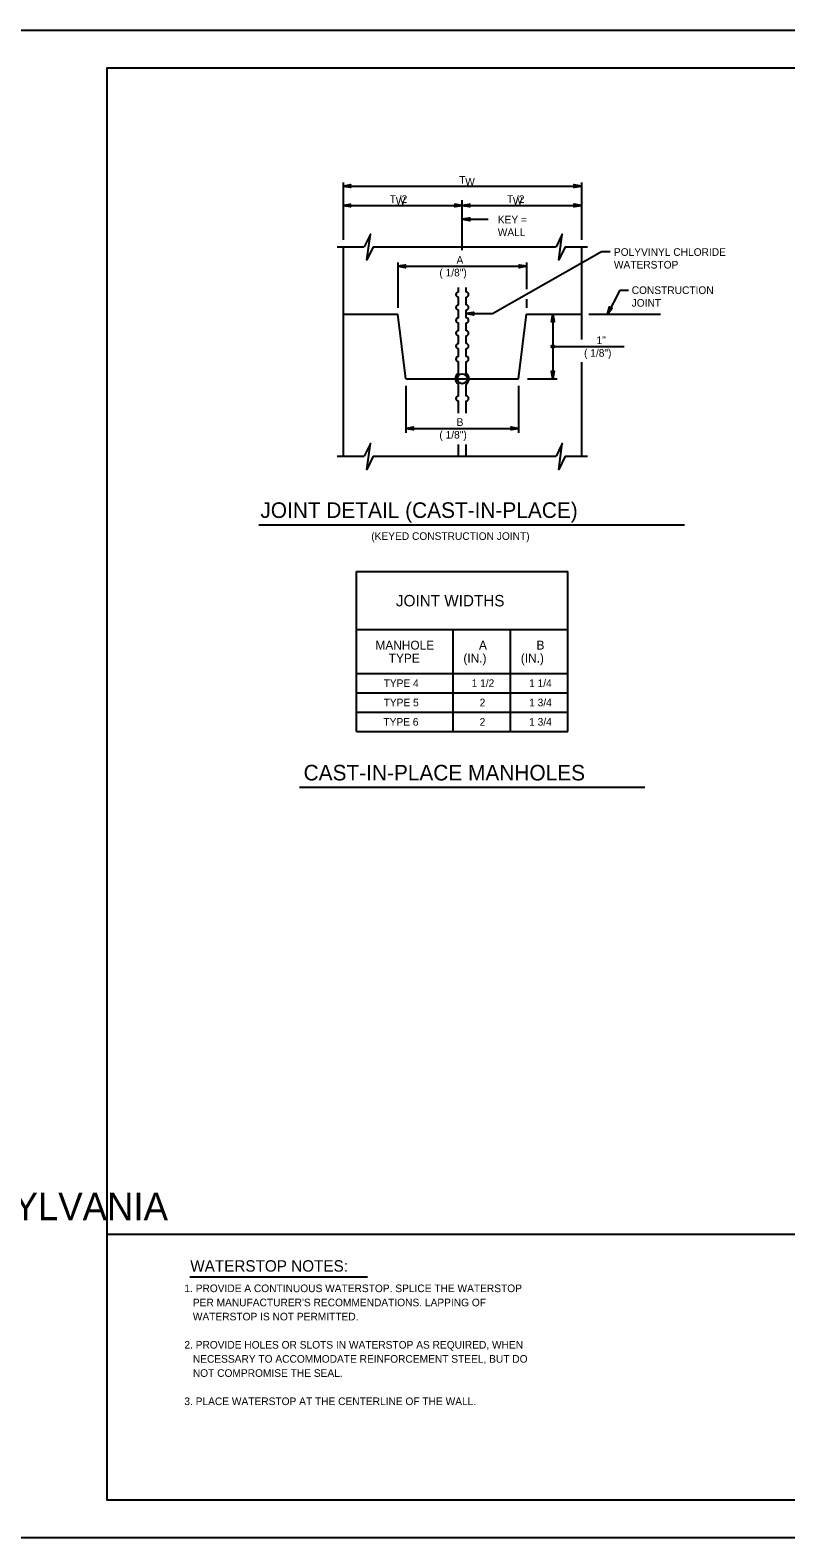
# Model space of a CAD drawing. Extents: x 2106427 to 2114911, y 988717 to 990787.
# Drawn here: x 2111974 to 2112951, y 988839 to 990787 of the extents above; entities that cross this region are included whole.
import ezdxf

# ---------------------------------------------------------------- set-up
doc = ezdxf.new("R2010")
doc.units = 0
for name, color, linetype in [('1', 7, 'Continuous'), ('3', 7, 'Continuous'), ('PLT-BNDY', 7, 'Continuous')]:
    doc.layers.add(name, color=color, linetype=linetype)

msp = doc.modelspace()

# ---------------------------------------------------------------- linework, layer by layer
at = {"layer": '1'}
for p, q in [((2112378.6, 990590.2), (2112378.6, 990516.5)), ((2112378.6, 990585.8), (2112686.7, 990585.8)), ((2112686.7, 990590.2), (2112686.7, 990516.5)), ((2112532.6, 990502.9), (2112532.6, 990567.6)), ((2112378.6, 990560.8), (2112532.6, 990560.8)), ((2112532.6, 990560.8), (2112686.7, 990560.8)), ((2112532.6, 990542.9), (2112566.2, 990542.9)), ((2112371, 990507.3), (2112406, 990507.3)), ((2112378.6, 990507.3), (2112378.6, 990236.6)), ((2112417.6, 990507.3), (2112654.2, 990507.3)), ((2112665.8, 990507.3), (2112694.5, 990507.3)), ((2112686.7, 990507.3), (2112686.7, 990387.6)), ((2112571.6, 990421), (2112712.8, 990501)), ((2112712.8, 990501), (2112724.1, 990501)), ((2112449.3, 990487.2), (2112449.3, 990428.6)), ((2112449.3, 990482.1), (2112615.9, 990482.1)), ((2112615.9, 990487.2), (2112615.9, 990452.5)), ((2112527.6, 990448.8), (2112527.6, 990454.8)), ((2112537.6, 990448.8), (2112537.6, 990454.8)), ((2112736.4, 990451.1), (2112720.4, 990420)), ((2112736.4, 990451.1), (2112747.7, 990451.1)), ((2112527.6, 990432.2), (2112527.6, 990442.3)), ((2112537.6, 990432.2), (2112537.6, 990442.3)), ((2112615.9, 990439.7), (2112615.9, 990428.6)), ((2112378.6, 990420), (2112449.3, 990420)), ((2112459.7, 990336.7), (2112449.3, 990420)), ((2112527.6, 990415.5), (2112527.6, 990425.7)), ((2112537.6, 990415.5), (2112537.6, 990425.7)), ((2112537.6, 990421), (2112571.6, 990421)), ((2112605.5, 990336.7), (2112615.9, 990420)), ((2112615.9, 990420), (2112686.7, 990420)), ((2112649.9, 990420), (2112649.9, 990336.7)), ((2112696.4, 990420), (2112789.2, 990420)), ((2112527.6, 990398.8), (2112527.6, 990409)), ((2112527.6, 990382.1), (2112527.6, 990392.3)), ((2112537.6, 990398.8), (2112537.6, 990409)), ((2112537.6, 990382.1), (2112537.6, 990392.3)), ((2112527.6, 990365.5), (2112527.6, 990375.7)), ((2112537.6, 990365.5), (2112537.6, 990375.7)), ((2112649.9, 990378.3), (2112742.2, 990378.3)), ((2112527.6, 990344), (2112527.6, 990359)), ((2112537.6, 990344), (2112537.6, 990359)), ((2112686.7, 990358.2), (2112686.7, 990236.6)), ((2112459.7, 990336.7), (2112605.5, 990336.7)), ((2112617.1, 990336.7), (2112655.6, 990336.7)), ((2112459.7, 990327.7), (2112459.7, 990267)), ((2112527.6, 990314.4), (2112527.6, 990329.4)), ((2112537.6, 990314.4), (2112537.6, 990329.4)), ((2112605.5, 990327.7), (2112605.5, 990267)), ((2112527.6, 990292.2), (2112527.6, 990308)), ((2112537.6, 990292.2), (2112537.6, 990308)), ((2112459.7, 990272.5), (2112605.5, 990272.5)), ((2112371, 990236.6), (2112406, 990236.6)), ((2112417.6, 990236.6), (2112654.2, 990236.6)), ((2112527.6, 990236.6), (2112527.6, 990251.8)), ((2112537.6, 990236.6), (2112537.6, 990251.8)), ((2112665.8, 990236.6), (2112694.5, 990236.6)), ((2112269.5, 990148.1), (2112820.2, 990148.1)), ((2112395.9, 989880.7), (2112395.9, 990087.4)), ((2112395.9, 990087.4), (2112669.4, 990087.4)), ((2112669.4, 989880.7), (2112669.4, 990087.4)), ((2112395.9, 990012.4), (2112669.4, 990012.4)), ((2112520.9, 989880.7), (2112520.9, 990012.4)), ((2112595.2, 989880.7), (2112595.2, 990012.4)), ((2112395.9, 989955.7), (2112669.4, 989955.7)), ((2112395.9, 989930.7), (2112669.4, 989930.7)), ((2112395.9, 989905.7), (2112669.4, 989905.7)), ((2112395.9, 989880.7), (2112669.4, 989880.7)), ((2112322.1, 989808.8), (2112768.6, 989808.8)), ((2112072.8, 989231), (2113995.4, 989231)), ((2112180.2, 989175.8), (2112410.3, 989175.8))]:
    msp.add_line(p, q, dxfattribs=at)
for points in [[(2114651.6, 988887.7), (2114651.6, 990738.1), (2112072.8, 990738.1), (2112072.8, 988887.7), (2114651.6, 988887.7), (2114651.6, 988974.2), (2113995.4, 988974.2), (2113995.4, 989186.4), (2114651.6, 989186.4), (2114651.6, 989281.4), (2113995.4, 989281.4), (2113995.4, 988887.7), (2114253.9, 988887.7), (2114253.9, 988974.2), (2114253.9, 988887.7), (2114506.6, 988887.7), (2114506.6, 988974.2), (2114506.6, 988933.8), (2114651.6, 988933.8)], [(2112378.6, 990585.8), (2112388.3, 990587.6), (2112388, 990587.4), (2112387.6, 990587.1), (2112387.4, 990586.8), (2112387.2, 990586.4), (2112387.1, 990586.1), (2112387.1, 990585.8), (2112387.1, 990585.5), (2112387.2, 990585.1), (2112387.4, 990584.8), (2112387.6, 990584.5), (2112388, 990584.2), (2112388.3, 990584), (2112378.6, 990585.8), (2112388, 990584.2), (2112387.6, 990584.5), (2112378.6, 990585.8), (2112387.4, 990584.8), (2112387.2, 990585.1), (2112378.6, 990585.8), (2112387.1, 990585.5), (2112387.1, 990585.8), (2112378.6, 990585.8), (2112387.1, 990586.1), (2112387.2, 990586.4), (2112378.6, 990585.8), (2112387.4, 990586.8), (2112387.6, 990587.1), (2112378.6, 990585.8), (2112388, 990587.4)], [(2112686.7, 990585.8), (2112676.9, 990584), (2112677.3, 990584.2), (2112677.7, 990584.5), (2112677.9, 990584.8), (2112678.1, 990585.1), (2112678.1, 990585.5), (2112678.2, 990585.8), (2112678.1, 990586.1), (2112678.1, 990586.4), (2112677.9, 990586.8), (2112677.7, 990587.1), (2112677.3, 990587.4), (2112676.9, 990587.6), (2112686.7, 990585.8), (2112677.3, 990587.4), (2112677.7, 990587.1), (2112686.7, 990585.8), (2112677.9, 990586.8), (2112678.1, 990586.4), (2112686.7, 990585.8), (2112678.1, 990586.1), (2112678.2, 990585.8), (2112686.7, 990585.8), (2112678.1, 990585.5), (2112678.1, 990585.1), (2112686.7, 990585.8), (2112677.9, 990584.8), (2112677.7, 990584.5), (2112686.7, 990585.8), (2112677.3, 990584.2)], [(2112378.6, 990560.8), (2112388.3, 990562.6), (2112388, 990562.4), (2112387.6, 990562.1), (2112387.4, 990561.8), (2112387.2, 990561.4), (2112387.1, 990561.1), (2112387.1, 990560.8), (2112387.1, 990560.5), (2112387.2, 990560.1), (2112387.4, 990559.8), (2112387.6, 990559.5), (2112388, 990559.2), (2112388.3, 990559), (2112378.6, 990560.8), (2112388, 990559.2), (2112387.6, 990559.5), (2112378.6, 990560.8), (2112387.4, 990559.8), (2112387.2, 990560.1), (2112378.6, 990560.8), (2112387.1, 990560.5), (2112387.1, 990560.8), (2112378.6, 990560.8), (2112387.1, 990561.1), (2112387.2, 990561.4), (2112378.6, 990560.8), (2112387.4, 990561.8), (2112387.6, 990562.1), (2112378.6, 990560.8), (2112388, 990562.4)], [(2112532.6, 990560.8), (2112522.9, 990559), (2112523.2, 990559.2), (2112523.6, 990559.5), (2112523.8, 990559.8), (2112524, 990560.1), (2112524.1, 990560.5), (2112524.1, 990560.8), (2112524.1, 990561.1), (2112524, 990561.4), (2112523.8, 990561.8), (2112523.6, 990562.1), (2112523.2, 990562.4), (2112522.9, 990562.6), (2112532.6, 990560.8), (2112523.2, 990562.4), (2112523.6, 990562.1), (2112532.6, 990560.8), (2112523.8, 990561.8), (2112524, 990561.4), (2112532.6, 990560.8), (2112524.1, 990561.1), (2112524.1, 990560.8), (2112532.6, 990560.8), (2112524.1, 990560.5), (2112524, 990560.1), (2112532.6, 990560.8), (2112523.8, 990559.8), (2112523.6, 990559.5), (2112532.6, 990560.8), (2112523.2, 990559.2)], [(2112532.6, 990560.8), (2112542.4, 990562.6), (2112542, 990562.4), (2112541.7, 990562.1), (2112541.5, 990561.8), (2112541.3, 990561.4), (2112541.2, 990561.1), (2112541.2, 990560.8), (2112541.2, 990560.5), (2112541.3, 990560.1), (2112541.5, 990559.8), (2112541.7, 990559.5), (2112542, 990559.2), (2112542.4, 990559), (2112532.6, 990560.8), (2112542, 990559.2), (2112541.7, 990559.5), (2112532.6, 990560.8), (2112541.5, 990559.8), (2112541.3, 990560.1), (2112532.6, 990560.8), (2112541.2, 990560.5), (2112541.2, 990560.8), (2112532.6, 990560.8), (2112541.2, 990561.1), (2112541.3, 990561.4), (2112532.6, 990560.8), (2112541.5, 990561.8), (2112541.7, 990562.1), (2112532.6, 990560.8), (2112542, 990562.4)], [(2112686.7, 990560.8), (2112676.9, 990559), (2112677.3, 990559.2), (2112677.7, 990559.5), (2112677.9, 990559.8), (2112678.1, 990560.1), (2112678.1, 990560.5), (2112678.2, 990560.8), (2112678.1, 990561.1), (2112678.1, 990561.4), (2112677.9, 990561.8), (2112677.7, 990562.1), (2112677.3, 990562.4), (2112676.9, 990562.6), (2112686.7, 990560.8), (2112677.3, 990562.4), (2112677.7, 990562.1), (2112686.7, 990560.8), (2112677.9, 990561.8), (2112678.1, 990561.4), (2112686.7, 990560.8), (2112678.1, 990561.1), (2112678.2, 990560.8), (2112686.7, 990560.8), (2112678.1, 990560.5), (2112678.1, 990560.1), (2112686.7, 990560.8), (2112677.9, 990559.8), (2112677.7, 990559.5), (2112686.7, 990560.8), (2112677.3, 990559.2)], [(2112532.6, 990542.9), (2112542.4, 990544.7), (2112542, 990544.4), (2112541.7, 990544.2), (2112541.5, 990543.8), (2112541.3, 990543.5), (2112541.2, 990543.2), (2112541.2, 990542.9), (2112541.2, 990542.5), (2112541.3, 990542.2), (2112541.5, 990541.9), (2112541.7, 990541.5), (2112542, 990541.3), (2112542.4, 990541), (2112532.6, 990542.9), (2112542, 990541.3), (2112541.7, 990541.5), (2112532.6, 990542.9), (2112541.5, 990541.9), (2112541.3, 990542.2), (2112532.6, 990542.9), (2112541.2, 990542.5), (2112541.2, 990542.9), (2112532.6, 990542.9), (2112541.2, 990543.2), (2112541.3, 990543.5), (2112532.6, 990542.9), (2112541.5, 990543.8), (2112541.7, 990544.2), (2112532.6, 990542.9), (2112542, 990544.4)], [(2112417.6, 990507.3), (2112409.2, 990490.3), (2112413.8, 990523.6), (2112406, 990507.3)], [(2112665.8, 990507.3), (2112657.4, 990490.3), (2112662, 990523.6), (2112654.2, 990507.3)], [(2112449.3, 990482.1), (2112459.1, 990483.9), (2112458.7, 990483.7), (2112458.4, 990483.4), (2112458.2, 990483.1), (2112458, 990482.8), (2112457.9, 990482.4), (2112457.9, 990482.1), (2112457.9, 990481.8), (2112458, 990481.4), (2112458.2, 990481.1), (2112458.4, 990480.8), (2112458.7, 990480.5), (2112459.1, 990480.3), (2112449.3, 990482.1), (2112458.7, 990480.5), (2112458.4, 990480.8), (2112449.3, 990482.1), (2112458.2, 990481.1), (2112458, 990481.4), (2112449.3, 990482.1), (2112457.9, 990481.8), (2112457.9, 990482.1), (2112449.3, 990482.1), (2112457.9, 990482.4), (2112458, 990482.8), (2112449.3, 990482.1), (2112458.2, 990483.1), (2112458.4, 990483.4), (2112449.3, 990482.1), (2112458.7, 990483.7)], [(2112615.9, 990482.1), (2112606.2, 990480.3), (2112606.5, 990480.5), (2112606.9, 990480.8), (2112607.1, 990481.1), (2112607.3, 990481.4), (2112607.4, 990481.8), (2112607.4, 990482.1), (2112607.4, 990482.4), (2112607.3, 990482.8), (2112607.1, 990483.1), (2112606.9, 990483.4), (2112606.5, 990483.7), (2112606.2, 990483.9), (2112615.9, 990482.1), (2112606.5, 990483.7), (2112606.9, 990483.4), (2112615.9, 990482.1), (2112607.1, 990483.1), (2112607.3, 990482.8), (2112615.9, 990482.1), (2112607.4, 990482.4), (2112607.4, 990482.1), (2112615.9, 990482.1), (2112607.4, 990481.8), (2112607.3, 990481.4), (2112615.9, 990482.1), (2112607.1, 990481.1), (2112606.9, 990480.8), (2112615.9, 990482.1), (2112606.5, 990480.5)], [(2112720.4, 990420), (2112723.3, 990429.5), (2112723.3, 990429.1), (2112723.4, 990428.6), (2112723.6, 990428.3), (2112723.8, 990428), (2112724.1, 990427.8), (2112724.3, 990427.6), (2112724.7, 990427.5), (2112725, 990427.4), (2112725.3, 990427.4), (2112725.7, 990427.4), (2112726.1, 990427.7), (2112726.5, 990427.9), (2112720.4, 990420), (2112726.1, 990427.7), (2112725.7, 990427.4), (2112720.4, 990420), (2112725.3, 990427.4), (2112725, 990427.4), (2112720.4, 990420), (2112724.7, 990427.5), (2112724.3, 990427.6), (2112720.4, 990420), (2112724.1, 990427.8), (2112723.8, 990428), (2112720.4, 990420), (2112723.6, 990428.3), (2112723.4, 990428.6), (2112720.4, 990420), (2112723.3, 990429.1)], [(2112537.6, 990421), (2112547.4, 990422.8), (2112547, 990422.5), (2112546.7, 990422.3), (2112546.5, 990421.9), (2112546.3, 990421.6), (2112546.2, 990421.3), (2112546.2, 990421), (2112546.2, 990420.6), (2112546.3, 990420.3), (2112546.5, 990420), (2112546.7, 990419.6), (2112547, 990419.4), (2112547.4, 990419.1), (2112537.6, 990421), (2112547, 990419.4), (2112546.7, 990419.6), (2112537.6, 990421), (2112546.5, 990420), (2112546.3, 990420.3), (2112537.6, 990421), (2112546.2, 990420.6), (2112546.2, 990421), (2112537.6, 990421), (2112546.2, 990421.3), (2112546.3, 990421.6), (2112537.6, 990421), (2112546.5, 990421.9), (2112546.7, 990422.3), (2112537.6, 990421), (2112547, 990422.5)], [(2112649.9, 990420), (2112651.7, 990410.2), (2112651.5, 990410.6), (2112651.2, 990411), (2112650.9, 990411.2), (2112650.6, 990411.4), (2112650.2, 990411.4), (2112649.9, 990411.5), (2112649.6, 990411.4), (2112649.2, 990411.4), (2112648.9, 990411.2), (2112648.6, 990411), (2112648.3, 990410.6), (2112648.1, 990410.2), (2112649.9, 990420), (2112648.3, 990410.6), (2112648.6, 990411), (2112649.9, 990420), (2112648.9, 990411.2), (2112649.2, 990411.4), (2112649.9, 990420), (2112649.6, 990411.4), (2112649.9, 990411.5), (2112649.9, 990420), (2112650.2, 990411.4), (2112650.6, 990411.4), (2112649.9, 990420), (2112650.9, 990411.2), (2112651.2, 990411), (2112649.9, 990420), (2112651.5, 990410.6)], [(2112649.9, 990336.7), (2112648.1, 990346.5), (2112648.3, 990346.1), (2112648.6, 990345.7), (2112648.9, 990345.5), (2112649.2, 990345.3), (2112649.6, 990345.3), (2112649.9, 990345.2), (2112650.2, 990345.3), (2112650.6, 990345.3), (2112650.9, 990345.5), (2112651.2, 990345.7), (2112651.5, 990346.1), (2112651.7, 990346.5), (2112649.9, 990336.7), (2112651.5, 990346.1), (2112651.2, 990345.7), (2112649.9, 990336.7), (2112650.9, 990345.5), (2112650.6, 990345.3), (2112649.9, 990336.7), (2112650.2, 990345.3), (2112649.9, 990345.2), (2112649.9, 990336.7), (2112649.6, 990345.3), (2112649.2, 990345.3), (2112649.9, 990336.7), (2112648.9, 990345.5), (2112648.6, 990345.7), (2112649.9, 990336.7), (2112648.3, 990346.1)], [(2112459.7, 990272.5), (2112469.5, 990274.4), (2112469.1, 990274.1), (2112468.8, 990273.8), (2112468.6, 990273.5), (2112468.4, 990273.2), (2112468.3, 990272.9), (2112468.3, 990272.5), (2112468.3, 990272.2), (2112468.4, 990271.9), (2112468.6, 990271.5), (2112468.8, 990271.2), (2112469.1, 990271), (2112469.5, 990270.7), (2112459.7, 990272.5), (2112469.1, 990271), (2112468.8, 990271.2), (2112459.7, 990272.5), (2112468.6, 990271.5), (2112468.4, 990271.9), (2112459.7, 990272.5), (2112468.3, 990272.2), (2112468.3, 990272.5), (2112459.7, 990272.5), (2112468.3, 990272.9), (2112468.4, 990273.2), (2112459.7, 990272.5), (2112468.6, 990273.5), (2112468.8, 990273.8), (2112459.7, 990272.5), (2112469.1, 990274.1)], [(2112605.5, 990272.5), (2112595.8, 990270.7), (2112596.1, 990271), (2112596.5, 990271.2), (2112596.7, 990271.5), (2112596.9, 990271.9), (2112597, 990272.2), (2112597, 990272.5), (2112597, 990272.9), (2112596.9, 990273.2), (2112596.7, 990273.5), (2112596.5, 990273.8), (2112596.1, 990274.1), (2112595.8, 990274.4), (2112605.5, 990272.5), (2112596.1, 990274.1), (2112596.5, 990273.8), (2112605.5, 990272.5), (2112596.7, 990273.5), (2112596.9, 990273.2), (2112605.5, 990272.5), (2112597, 990272.9), (2112597, 990272.5), (2112605.5, 990272.5), (2112597, 990272.2), (2112596.9, 990271.9), (2112605.5, 990272.5), (2112596.7, 990271.5), (2112596.5, 990271.2), (2112605.5, 990272.5), (2112596.1, 990271)], [(2112417.6, 990236.6), (2112409.2, 990219.6), (2112413.8, 990252.9), (2112406, 990236.6)], [(2112665.8, 990236.6), (2112657.4, 990219.6), (2112662, 990252.9), (2112654.2, 990236.6)]]:
    msp.add_lwpolyline(points, dxfattribs=at)
for centre, radius in [((2112649.9, 990378.3), 1.75), ((2112649.9, 990378.3), 1.31), ((2112649.9, 990378.3), 0.875), ((2112649.9, 990378.3), 0.437), ((2112532.6, 990336.7), 6.34)]:
    msp.add_circle(centre, radius, dxfattribs=at)
for centre, radius, start, end in [((2112527.6, 990445.6), 3.24, 90, 270), ((2112537.7, 990445.6), 3.24, 270, 90), ((2112527.6, 990428.9), 3.24, 90, 270), ((2112537.7, 990428.9), 3.24, 270, 90), ((2112527.6, 990412.2), 3.24, 90, 270), ((2112537.7, 990412.2), 3.24, 270, 90), ((2112527.6, 990395.6), 3.24, 90, 270), ((2112537.7, 990395.6), 3.24, 270, 90), ((2112527.6, 990378.9), 3.24, 90, 270), ((2112537.7, 990378.9), 3.24, 270, 90), ((2112527.6, 990362.2), 3.24, 90, 270), ((2112537.7, 990362.2), 3.24, 270, 90), ((2112532.6, 990336.7), 8.83, 124.5073, 235.4927), ((2112532.6, 990336.7), 8.83, 304.5073, 55.4927), ((2112527.6, 990311.2), 3.24, 90, 270), ((2112537.7, 990311.2), 3.24, 270, 90)]:
    msp.add_arc(centre, radius, start, end, dxfattribs=at)
at = {"layer": 'PLT-BNDY'}
msp.add_lwpolyline([(2111944.9, 990787.3), (2114704.1, 990787.3), (2114704.1, 988838.5), (2111944.9, 988838.5)], close=True, dxfattribs=at)

# ---------------------------------------------------------------- texts
at = {"layer": '3'}
for s, height, p in [('T ', 9.84, (2112528.8, 990588.8)), ('W', 9.84, (2112536.5, 990586.5)), ('T /2', 9.84, (2112438.9, 990564)), ('W', 9.84, (2112446.7, 990561.8)), ('T /2', 9.84, (2112590.5, 990564)), ('W', 9.84, (2112598.2, 990561.8)), ('  KEY =', 9.84, (2112571.3, 990537.6)), ('  KEY =', 9.84, (2112571.3, 990537.6)), ('  WALL', 9.84, (2112571.3, 990521.2)), ('  WALL', 9.84, (2112571.3, 990521.2)), ('A', 9.84, (2112525.2, 990485.4)), ('WATERSTOP', 9.84, (2112728.8, 990479.2)), ('POLYVINYL CHLORIDE', 9.843, (2112728.8, 990495.6)), ('( 1/8")', 9.84, (2112503.1, 990469)), ('CONSTRUCTION', 9.843, (2112751.8, 990446.3)), ('JOINT', 9.84, (2112751.8, 990429.9)), ('1"', 9.84, (2112706.3, 990381.6)), ('( 1/8")', 9.84, (2112690.2, 990365.2)), ('B', 9.84, (2112525.4, 990275.8)), ('( 1/8")', 9.84, (2112503.1, 990259.4)), ('JOINT DETAIL (CAST-IN-PLACE)', 20.158, (2112271.6, 990156.8)), ('(KEYED CONSTRUCTION JOINT)', 9.843, (2112415, 990128.4)), ('JOINT WIDTHS', 14.764, (2112446.9, 990042.5)), ('MANHOLE', 11.48, (2112420.4, 989986.6)), ('TYPE', 11.48, (2112437.6, 989969.8)), ('(IN.)', 11.48, (2112534.1, 989969.9)), ('A', 11.5, (2112554.3, 989986.7)), ('(IN.)', 11.48, (2112608.4, 989969.9)), ('B', 11.5, (2112628.7, 989986.7)), ('TYPE 4', 9.84, (2112431, 989938.3)), ('1 1/2', 9.84, (2112544.8, 989938.3)), ('1 1/4', 9.84, (2112619.1, 989938.3)), ('TYPE 5', 9.84, (2112431, 989913.3)), ('2', 9.84, (2112555.2, 989913.3)), ('1 3/4', 9.84, (2112619.2, 989913.3)), ('TYPE 6', 9.84, (2112430.7, 989888.3)), ('2', 9.84, (2112555.2, 989888.3)), ('1 3/4', 9.84, (2112619.2, 989888.3)), ('CAST-IN-PLACE MANHOLES', 20.158, (2112327.5, 989817.5)), ('COMMONWEALTH OF PENNSYLVANIA', 35.379, (2111279.4, 989249.1)), ('WATERSTOP NOTES:', 14.764, (2112180.9, 989182.6)), (' 1. PROVIDE A CONTINUOUS WATERSTOP. SPLICE THE WATERSTOP', 9.843, (2112169.6, 989156.1)), ("    PER MANUFACTURER'S RECOMMENDATIONS. LAPPING OF", 9.843, (2112169.6, 989137.8)), ('    WATERSTOP IS NOT PERMITTED.', 9.843, (2112169.6, 989119.6)), (' 2. PROVIDE HOLES OR SLOTS IN WATERSTOP AS REQUIRED, WHEN', 9.843, (2112169.6, 989083.1)), ('    NECESSARY TO ACCOMMODATE REINFORCEMENT STEEL, BUT DO', 9.843, (2112169.6, 989064.9)), ('    NOT COMPROMISE THE SEAL.', 9.843, (2112169.6, 989046.6)), (' 3. PLACE WATERSTOP AT THE CENTERLINE OF THE WALL.', 9.843, (2112169.6, 989010.1))]:
    msp.add_text(s, height=height, dxfattribs=at).set_placement(p)

doc.saveas('drawing.dxf')
